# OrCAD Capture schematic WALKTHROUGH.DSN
size A; title: PSpice Walkthrough; rev: A; company: EMA Design Automation; note: EMA-12345678; note: 225 Tech Park Dr; note: Rochester, NY
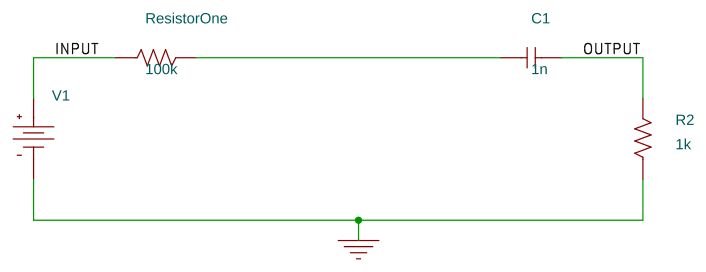
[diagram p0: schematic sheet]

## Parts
C1  1n  [cap196]
R2  1k  [AXRC05]
ResistorOne  100k  [AXRC05]
V1  VDC

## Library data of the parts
C1 = C
R2 ResistorOne = R
V1 = VDC

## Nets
0: R2.1 V1.1(-)
INPUT: ResistorOne.1 V1.0(+)
OUTPUT: C1.2 R2.2
N00358: C1.1 ResistorOne.2
